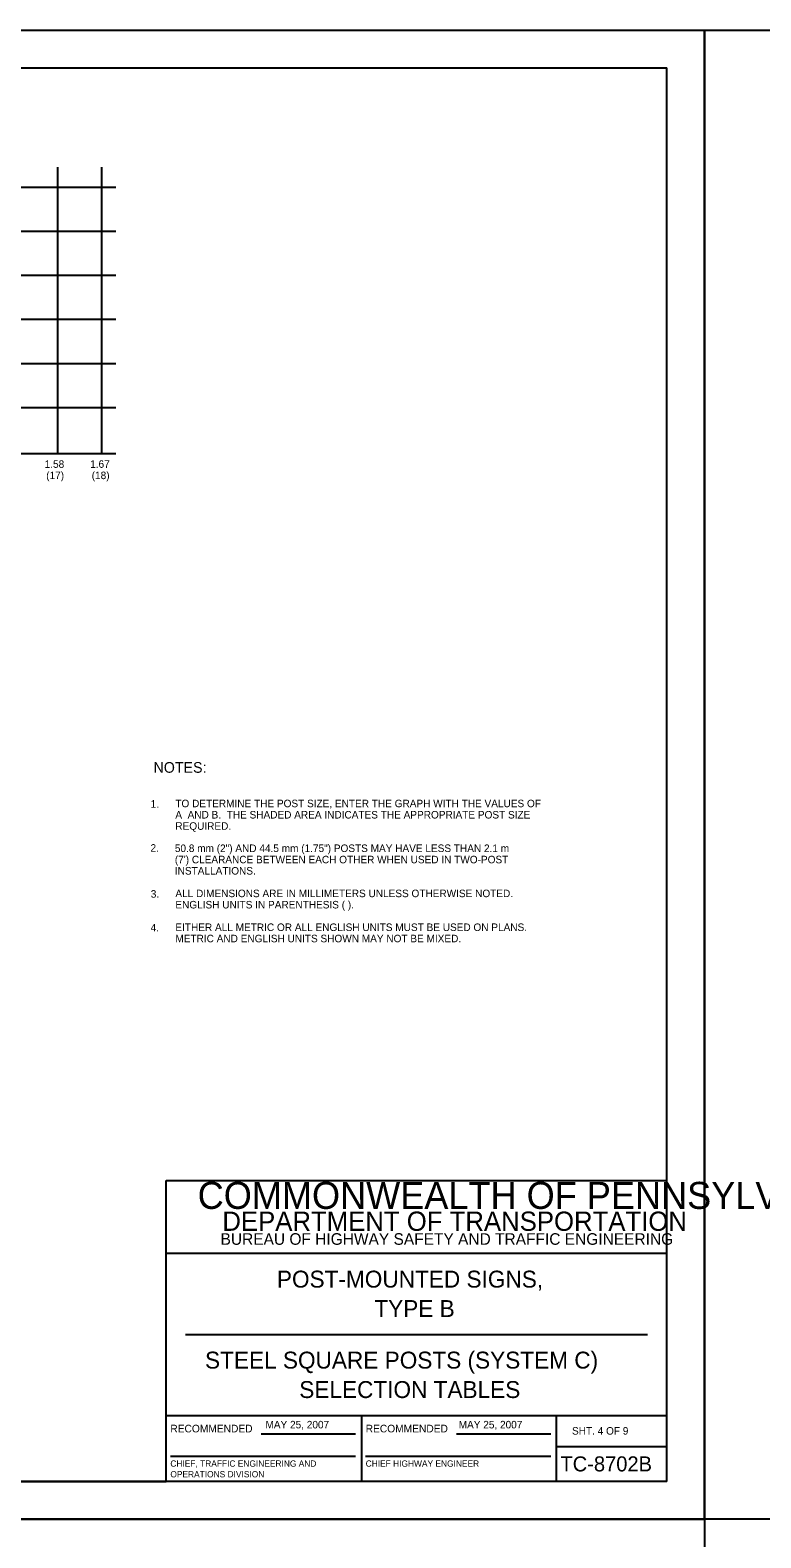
# Model space of a CAD drawing. Extents: x 644358 to 648627, y 294594 to 295782.
# Drawn here: x 647453 to 647745, y 295180 to 295782 of the extents above; entities that cross this region are included whole.
import ezdxf

# ---------------------------------------------------------------- set-up
doc = ezdxf.new("R2010")
doc.units = 0
for name, color, linetype in [('1', 7, 'Continuous'), ('2', 7, 'Continuous'), ('4', 7, 'Continuous'), ('PLT-BNDY', 7, 'Continuous')]:
    doc.layers.add(name, color=color, linetype=linetype)

msp = doc.modelspace()

# ---------------------------------------------------------------- linework, layer by layer
at = {"layer": '1'}
for p, q in [((646921.31, 295766.63), (647707.31, 295766.63)), ((647707.31, 295202.63), (647707.31, 295766.63)), ((647507.31, 295202.63), (647507.31, 295322.63)), ((647507.31, 295322.63), (647707.31, 295322.63)), ((647707.31, 295293.63), (647507.31, 295293.63)), ((647515.06, 295261.31), (647699.56, 295261.31)), ((647507.31, 295229), (647707.31, 295229)), ((647585.31, 295229), (647585.31, 295202.63)), ((647663.19, 295202.63), (647663.19, 295229)), ((647545.24, 295221.57), (647582.87, 295221.57)), ((647623.24, 295221.57), (647660.87, 295221.57)), ((647663.19, 295216.63), (647707.31, 295216.63)), ((647508.99, 295212.68), (647582.87, 295212.68)), ((647586.99, 295212.68), (647660.87, 295212.68)), ((647707.31, 295202.63), (646921.31, 295202.63)), ((646921.31, 295202.63), (647507.31, 295202.63))]:
    msp.add_line(p, q, dxfattribs=at)
at = {"layer": '2'}
for p, q in [((647464.03, 295612.54), (647464.03, 295726.91)), ((647481.66, 295612.54), (647481.66, 295726.91)), ((647487.16, 295718.91), (647252.91, 295718.91)), ((647487.16, 295701.29), (647252.91, 295701.29)), ((647487.16, 295683.79), (647252.91, 295683.79)), ((647487.16, 295666.16), (647252.91, 295666.16)), ((647252.91, 295648.66), (647487.16, 295648.66)), ((647309.27, 295631.04), (647487.16, 295631.04)), ((647487.16, 295612.54), (647252.91, 295612.54))]:
    msp.add_line(p, q, dxfattribs=at)
at = {"layer": 'PLT-BNDY'}
for points in [[(646881.31, 295781.63), (647722.31, 295781.63), (647722.31, 295187.63), (646881.31, 295187.63)], [(647722.31, 295781.63), (648563.31, 295781.63), (648563.31, 295187.63), (647722.31, 295187.63)], [(646881.31, 295187.63), (647722.31, 295187.63), (647722.31, 294593.63), (646881.31, 294593.63)]]:
    msp.add_lwpolyline(points, close=True, dxfattribs=at)

# ---------------------------------------------------------------- texts
at = {"layer": '1'}
for s, height, p in [('1. ', 3.089, (647501.08, 295471.38)), ('2. ', 3, (647501.07, 295453.86)), ('3. ', 3, (647501.17, 295435.53)), ('4. ', 3, (647501.11, 295422.07)), ('COMMONWEALTH OF PENNSYLVANIA', 10.7828, (647519.9, 295311.36)), ('DEPARTMENT OF TRANSPORTATION', 7.6837, (647529.76, 295302.61)), ('BUREAU OF HIGHWAY SAFETY AND TRAFFIC ENGINEERING', 4.6253, (647529.04, 295297.04)), ('POST-MOUNTED SIGNS,', 6.75, (647551.54, 295279.97)), ('TYPE B', 6.75, (647590.45, 295268.22)), ('STEEL SQUARE POSTS (SYSTEM C)', 6.75, (647522.84, 295247.66)), ('SELECTION TABLES', 6.75, (647560.47, 295235.91)), ('RECOMMENDED', 3.048, (647508.99, 295222.2)), ('RECOMMENDED', 3.048, (647586.99, 295222.2)), ('SHT. 4 OF 9', 3, (647669.39, 295221.31)), ('CHIEF, TRAFFIC ENGINEERING AND', 2.5, (647508.99, 295208.51)), ('CHIEF HIGHWAY ENGINEER', 2.5, (647586.99, 295208.51)), ('TC-8702B', 6, (647664.77, 295206.63)), ('OPERATIONS DIVISION', 2.5, (647508.99, 295204.26))]:
    msp.add_text(s, height=height, dxfattribs=at).set_placement(p)
at = {"layer": '2'}
for s, p in [('A  AND B.  THE SHADED AREA INDICATES THE APPROPRIATE POST SIZE ', (647510.98, 295467.11)), ('TO DETERMINE THE POST SIZE, ENTER THE GRAPH WITH THE VALUES OF ', (647510.98, 295471.61)), ('REQUIRED.', (647510.98, 295462.61)), ('50.8 mm (2") AND 44.5 mm (1.75") POSTS MAY HAVE LESS THAN 2.1 m', (647510.79, 295453.74)), ("(7') CLEARANCE BETWEEN EACH OTHER WHEN USED IN TWO-POST", (647510.79, 295449.24)), ('INSTALLATIONS.', (647510.79, 295444.74)), ('ALL DIMENSIONS ARE IN MILLIMETERS UNLESS OTHERWISE NOTED.  ', (647511, 295435.73)), ('ENGLISH UNITS IN PARENTHESIS ( ).', (647511, 295431.23)), ('EITHER ALL METRIC OR ALL ENGLISH UNITS MUST BE USED ON PLANS.  ', (647511, 295422.23)), ('METRIC AND ENGLISH UNITS SHOWN MAY NOT BE MIXED.', (647511, 295417.73)), ('MAY 25, 2007', (647546.98, 295223.79)), ('MAY 25, 2007', (647624.14, 295223.79))]:
    msp.add_text(s, height=3, dxfattribs=at).set_placement(p)
at = {"layer": '4'}
for s, height, p in [('1.58', 3, (647458.8, 295607.01)), ('1.67', 3, (647476.97, 295607.01)), ('(17)', 3, (647459.42, 295602.51)), ('(18)', 3, (647477.59, 295602.51)), ('NOTES:', 4.25, (647502.27, 295485.36))]:
    msp.add_text(s, height=height, dxfattribs=at).set_placement(p)

doc.saveas('drawing.dxf')
